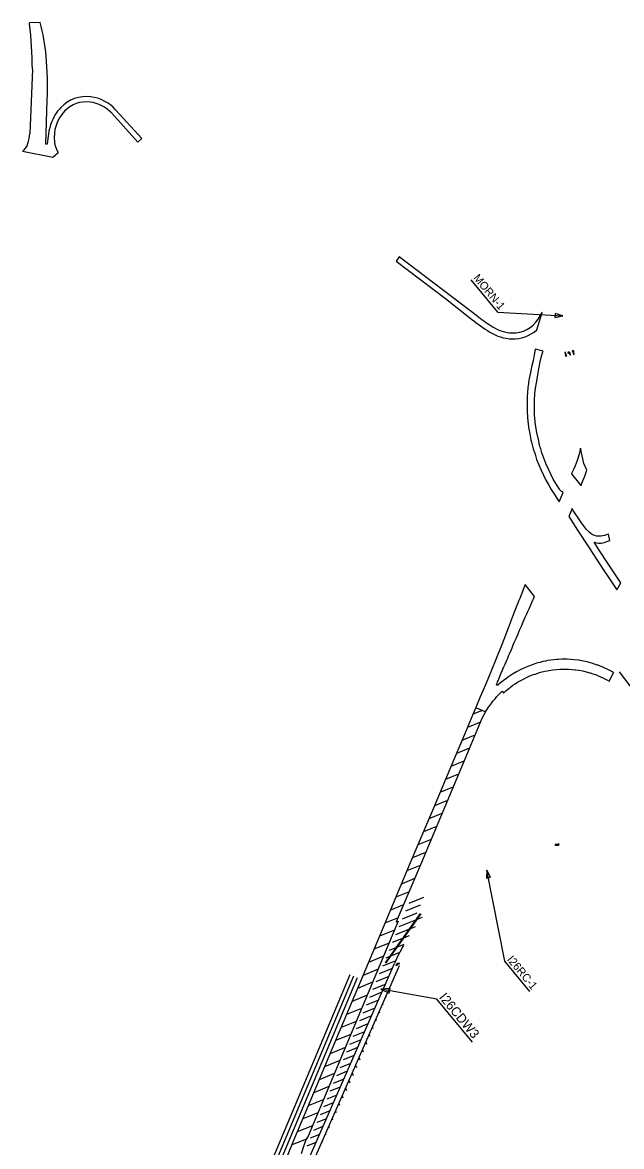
# Model space of a CAD drawing. Extents: x 1966356 to 1974207, y 790684 to 800034.
# Drawn here: x 1967744 to 1969541, y 796663 to 800034 of the extents above; entities that cross this region are included whole.
import ezdxf

# ---------------------------------------------------------------- set-up
doc = ezdxf.new("R2010")
doc.units = 0
for name, color, linetype in [('RD_EX_Pavement_Markings', 7, 'Continuous'), ('RD_PD_ALT5_LnLine', 7, 'Continuous'), ('RD_QTY_RemExConc', 7, 'Continuous'), ('RD_TX_RoadID', 7, 'Continuous'), ('TR_WZ_Temp Conc Barrier', 7, 'Continuous')]:
    doc.layers.add(name, color=color, linetype=linetype)

msp = doc.modelspace()

# ---------------------------------------------------------------- linework, layer by layer
at = {"layer": 'RD_EX_Pavement_Markings'}
for p, q in [((1968725.9, 797177.9), (1968434.7, 796483.7)), ((1968737, 797173.5), (1968445.8, 796479)), ((1968748.2, 797169), (1968456.8, 796474.4))]:
    msp.add_line(p, q, dxfattribs=at)
at = {"layer": 'RD_PD_ALT5_LnLine'}
for p, q in [((1969534, 798086.5), (1969927.6, 797568.6)), ((1969104.1, 797979.3), (1969095.1, 797957.9)), ((1969124.4, 797970.8), (1969095.5, 797959)), ((1969104.1, 797979.3), (1969133.7, 797966.8)), ((1969095.1, 797957.9), (1969070.2, 797898.8)), ((1969118.1, 797935.8), (1969079, 797919.8)), ((1969070.2, 797898.8), (1969050.4, 797851.9)), ((1969101.6, 797896.6), (1969062.5, 797880.6)), ((1969050.4, 797851.9), (1969031.1, 797806)), ((1969085, 797857.4), (1969046, 797841.5)), ((1969031.1, 797806), (1968977, 797677.9)), ((1969068.5, 797818.3), (1969029.5, 797802.3)), ((1969052, 797779.1), (1969013, 797763.1)), ((1969035.6, 797740), (1968996.5, 797724)), ((1969019.2, 797700.8), (1968979.9, 797684.8)), ((1968977, 797677.9), (1968924.5, 797553.2)), ((1969002.7, 797661.7), (1968963.4, 797645.6)), ((1968986.3, 797622.6), (1968947, 797606.5)), ((1968969.9, 797583.4), (1968930.5, 797567.3)), ((1968924.5, 797553.2), (1968907.7, 797513.1)), ((1968953.5, 797544.3), (1968914, 797528.2)), ((1968907.7, 797513.1), (1968828.6, 797325)), ((1968937, 797505.2), (1968897.6, 797489.1)), ((1968920.5, 797466), (1968881.1, 797449.9)), ((1968903.9, 797426.8), (1968864.7, 797410.8)), ((1968947.5, 797409.8), (1968903, 797391.6)), ((1968887.4, 797387.6), (1968848.2, 797371.6)), ((1968927.8, 797362.8), (1968883.3, 797344.6)), ((1968937.7, 797386.3), (1968893.2, 797368.1)), ((1968828.6, 797325), (1968760.5, 797163)), ((1968870.9, 797348.5), (1968831.7, 797332.5)), ((1968943.8, 797349.9), (1968873.5, 797321.1)), ((1968860.4, 797311.8), (1968815.3, 797293.3)), ((1968904.5, 797294.9), (1968853.8, 797274.2)), ((1968922.6, 797321.8), (1968863.6, 797297.7)), ((1968844, 797272.7), (1968798.8, 797254.2)), ((1968888.4, 797268.9), (1968843.9, 797250.7)), ((1968827.6, 797233.5), (1968782.4, 797215)), ((1968875.6, 797244.2), (1968834.1, 797227.2)), ((1968541.9, 796446), (1968875, 797205.5)), ((1968571.4, 796553.1), (1968860.3, 797212)), ((1968811.1, 797194.4), (1968765.9, 797175.9)), ((1968853.4, 797196.2), (1968814.4, 797180.3)), ((1968863.9, 797220), (1968824.2, 797203.8)), ((1968760.5, 797163), (1968694.6, 797006.4)), ((1968794.7, 797155.3), (1968749.5, 797136.8)), ((1968843, 797172.5), (1968804.6, 797156.8)), ((1968822.2, 797125.1), (1968784.9, 797109.9)), ((1968832.6, 797148.8), (1968794.7, 797133.3)), ((1968778.3, 797116.1), (1968733, 797097.6)), ((1968811.9, 797101.4), (1968775, 797086.4)), ((1968824.2, 797089.8), (1968825.3, 797087.3)), ((1968834.3, 797112.8), (1968835.1, 797110.8)), ((1968761.8, 797077), (1968716.5, 797058.5)), ((1968801.5, 797077.8), (1968765.2, 797062.9)), ((1968814.2, 797066.9), (1968815.4, 797063.8)), ((1968745.4, 797037.9), (1968700, 797019.3)), ((1968780.7, 797030.4), (1968745.5, 797016)), ((1968791.1, 797054.1), (1968755.3, 797039.4)), ((1968794, 797021), (1968795.7, 797016.9)), ((1968804.1, 797043.9), (1968805.6, 797040.3)), ((1968694.6, 797006.4), (1968593.6, 796765.9)), ((1968729, 796998.7), (1968683.6, 796980.2)), ((1968770.3, 797006.7), (1968735.6, 796992.5)), ((1968784, 796998), (1968785.9, 796993.4)), ((1968712.6, 796959.6), (1968667.2, 796941)), ((1968749.5, 796959.3), (1968715.9, 796945.5)), ((1968759.9, 796983), (1968725.8, 796969)), ((1968773.9, 796975.1), (1968776, 796969.9)), ((1968696.1, 796920.5), (1968650.7, 796901.9)), ((1968739.1, 796935.6), (1968706.1, 796922.1)), ((1968753.8, 796929.2), (1968756.4, 796923)), ((1968763.9, 796952.2), (1968766.2, 796946.4)), ((1968718.3, 796888.2), (1968686.4, 796875.1)), ((1968728.7, 796911.9), (1968696.3, 796898.6)), ((1968743.7, 796906.3), (1968746.5, 796899.5)), ((1968679.7, 796881.3), (1968634.3, 796862.8)), ((1968707.9, 796864.5), (1968676.6, 796851.6)), ((1968723.6, 796860.4), (1968726.5, 796853.3)), ((1968733.7, 796883.3), (1968736.7, 796876)), ((1968663.3, 796842.2), (1968617.9, 796823.6)), ((1968697.6, 796840.8), (1968666.7, 796828.2)), ((1968713.6, 796837.4), (1968716.1, 796831.1)), ((1968646.8, 796803.1), (1968601.5, 796784.5)), ((1968676.8, 796793.4), (1968647, 796781.2)), ((1968687.2, 796817.1), (1968656.9, 796804.7)), ((1968693.4, 796791.5), (1968695.4, 796786.7)), ((1968703.5, 796814.5), (1968705.8, 796808.9)), ((1968593.6, 796765.9), (1968557.8, 796680.2)), ((1968630.4, 796763.9), (1968585.1, 796745.4)), ((1968666.4, 796769.7), (1968637.2, 796757.7)), ((1968683.4, 796768.6), (1968685, 796764.5)), ((1968614, 796724.8), (1968568.7, 796706.3)), ((1968645.6, 796722.3), (1968617.5, 796710.8)), ((1968656, 796746), (1968627.3, 796734.3)), ((1968663.2, 796722.7), (1968664.3, 796720.1)), ((1968673.3, 796745.6), (1968674.7, 796742.3)), ((1968596, 796685), (1968552.4, 796667.2)), ((1968635.2, 796698.6), (1968607.6, 796687.3)), ((1968653.2, 796699.7), (1968653.9, 796697.9)), ((1968557.8, 796680.2), (1968491, 796520.4)), ((1968624.8, 796674.9), (1968597.8, 796663.8)), ((1968643.1, 796676.8), (1968643.6, 796675.7))]:
    msp.add_line(p, q, dxfattribs=at)
for points in [[(1969373.5, 799044.7), (1969371.2, 799044.1), (1969373.5, 799035.2), (1969371.9, 799034.8), (1969375.3, 799032.7), (1969377.4, 799036.2), (1969375.8, 799035.8)], [(1969388.5, 799037.3), (1969387.2, 799042.5), (1969383.4, 799044.8), (1969384.2, 799046.2), (1969380.3, 799045.2), (1969381.3, 799041.3), (1969382.2, 799042.7), (1969385.1, 799040.9), (1969386.2, 799036.7)], [(1969397.3, 799038.3), (1969399.6, 799038.9), (1969397.4, 799047.8), (1969399, 799048.2), (1969395.5, 799050.2), (1969393.5, 799046.8), (1969395.1, 799047.2)], [(1969342.5, 797568.7), (1969342.7, 797566.3), (1969351.8, 797566.8), (1969351.9, 797565.2), (1969354.6, 797568.2), (1969351.6, 797570.8), (1969351.7, 797569.2)], [(1968865.3, 797205.8), (1968867.3, 797210.7), (1968871.5, 797212.4), (1968870.9, 797213.9), (1968874.6, 797212.4), (1968873, 797208.7), (1968872.4, 797210.2), (1968869.2, 797208.9), (1968867.5, 797204.9)]]:
    msp.add_lwpolyline(points, close=True, dxfattribs=at)
msp.add_lwpolyline([(1969133.7, 797966.8), (1969122.6, 797946.3), (1969099.5, 797891.6), (1969079.1, 797843.5), (1968964, 797569.4), (1968944, 797521.7), (1968865.8, 797336.4), (1968871.5, 797338.1), (1968600.9, 796693.7), (1968594.7, 796682.8), (1968588.5, 796665.2), (1968580, 796640.7)], dxfattribs=at)
msp.add_arc((1969424.5, 796964.6), 616, 150.713, 156.3246, dxfattribs=at)
at = {"layer": 'RD_QTY_RemExConc'}
for p, q in [((1967797.2, 800034.1), (1967765.4, 800033.5)), ((1967774, 799894.3), (1967770.3, 799796.3)), ((1967770.3, 799796.3), (1967766, 799701.3)), ((1967814, 799669.5), (1967818.9, 799801.7)), ((1968012, 799761.7), (1968090.4, 799675.1)), ((1968102.3, 799685.9), (1968023.9, 799772.4)), ((1968090.4, 799675.1), (1968102.3, 799685.9)), ((1967818.8, 799669.2), (1967814, 799669.5)), ((1967744.4, 799647.6), (1967835.1, 799629.9)), ((1967835.1, 799629.9), (1967851.8, 799643.7)), ((1968874.6, 799331.3), (1968864.9, 799318.6)), ((1968864.9, 799318.6), (1969013.4, 799205.9)), ((1969111.8, 799151.3), (1968874.6, 799331.3)), ((1969013.4, 799205.9), (1969091.2, 799144.5)), ((1969287.1, 799111.9), (1969303.4, 799164.6)), ((1969303.4, 799164.6), (1969302.4, 799164.7)), ((1969306.3, 799048.4), (1969282.4, 799054)), ((1969393, 798575.9), (1969382.9, 798551.9)), ((1969506.8, 798480.8), (1969502.2, 798499.7)), ((1969280.1, 798312.8), (1969252.6, 798348.5)), ((1969527.3, 798332.3), (1969539.4, 798353.8)), ((1969280, 798312.7), (1969280.1, 798312.8)), ((1969257.6, 798260.4), (1969260.4, 798267)), ((1969517, 798084), (1969504, 798058.4)), ((1969504, 798058.4), (1969517, 798084)), ((1969104.1, 797979.3), (1969133.7, 797966.8))]:
    msp.add_line(p, q, dxfattribs=at)
for points in [[(1967859, 799778.9), (1967859, 799778.9)], [(1967870.6, 799767.9), (1967870.6, 799767.9)], [(1969282.4, 799054), (1969279.4, 799037.2), (1969276.3, 799019.7), (1969272.5, 799005.2), (1969267.9, 798984.7), (1969264.4, 798966), (1969263.5, 798960.7), (1969262.7, 798955.4), (1969262, 798950.1), (1969261.3, 798944.8), (1969260.7, 798939.4), (1969260.1, 798934.1), (1969259.6, 798928.7), (1969259.2, 798923.4), (1969259, 798920.9), (1969258.7, 798915.4), (1969258.4, 798909.8), (1969258.2, 798904.3), (1969258, 798898.7), (1969258, 798893.2), (1969257.9, 798887.6), (1969258, 798882), (1969258, 798878.2), (1969258.2, 798872.4), (1969258.4, 798866.5), (1969258.7, 798860.7), (1969258.9, 798858.1), (1969259.3, 798852.4), (1969259.7, 798846.6), (1969260.2, 798840.9), (1969260.8, 798835.1), (1969260.9, 798834.3), (1969261.5, 798828.7), (1969262.2, 798823.2), (1969262.6, 798820.6), (1969266, 798800), (1969269.5, 798782.7), (1969271.2, 798775.1), (1969276.8, 798754.8), (1969281.9, 798739.1), (1969286.6, 798723.7), (1969292.9, 798706.9), (1969300.2, 798691), (1969306.9, 798676.1), (1969314.8, 798660.9), (1969323, 798646.2), (1969330.6, 798632.8), (1969340.1, 798618.2), (1969354.5, 798596)], [(1969366.1, 798623.9), (1969363.1, 798626.3), (1969361.4, 798627.6), (1969360.4, 798628.3), (1969359.4, 798629.2), (1969358.4, 798630.1), (1969357.4, 798631.1), (1969356.5, 798632.1), (1969355.7, 798633.1), (1969354.9, 798634.2), (1969346, 798647.8), (1969336.5, 798664.6), (1969329.3, 798678.9), (1969322, 798694.3), (1969314.8, 798711), (1969308.5, 798727.3), (1969302.7, 798743.7), (1969301.6, 798746.9), (1969300.3, 798750.8), (1969299.1, 798754.8), (1969297.9, 798758.7), (1969296.8, 798762.7), (1969291.9, 798783.1), (1969287.3, 798804.7), (1969283.5, 798827.4), (1969281.5, 798845.9), (1969280.8, 798857.6), (1969280.1, 798877.3), (1969280.3, 798900), (1969281.5, 798920.4), (1969283.6, 798936.9), (1969287, 798957.9), (1969290.2, 798977.4), (1969293, 798995.2), (1969296.1, 799011.2), (1969300.3, 799030.4), (1969305.6, 799046.5), (1969306.3, 799048.4)], [(1969418.7, 798757.5), (1969414.4, 798738.8), (1969408.5, 798720.1), (1969402.3, 798704.4), (1969397.2, 798693.4), (1969392.8, 798683), (1969391.8, 798680.6)], [(1969437.5, 798691.5), (1969427.9, 798711.6), (1969418.7, 798757.5)], [(1969391.8, 798680.6), (1969391.8, 798680.6), (1969419.1, 798645)], [(1969419.9, 798645.7), (1969422.5, 798652.5), (1969425.4, 798659.7), (1969431.1, 798673.3), (1969437.5, 798691.5)], [(1969354.5, 798596), (1969354.7, 798596.4), (1969366.1, 798623.9)], [(1969502.2, 798499.7), (1969501.4, 798499.2), (1969499.2, 798498.1), (1969490.6, 798495), (1969485, 798494.1), (1969479.3, 798493.5), (1969473.6, 798493.3), (1969467.9, 798493.5), (1969466, 798493.6), (1969461.7, 798494.9), (1969457.6, 798496.5), (1969453.6, 798498.5), (1969450.5, 798500.3), (1969444.8, 798505), (1969439.4, 798509.9), (1969435.1, 798514.2), (1969419.3, 798536.2), (1969396.7, 798570.3), (1969393, 798575.9)], [(1969382.9, 798551.9), (1969409.5, 798511.2), (1969443.9, 798458.2), (1969486.7, 798393.5), (1969503.5, 798368.2), (1969527.3, 798332.3)], [(1969539.4, 798353.8), (1969527.2, 798371.8), (1969499.6, 798413.6), (1969474.8, 798451.3), (1969459.1, 798475.1), (1969463.2, 798473.9), (1969467.5, 798473), (1969471.9, 798472.5), (1969476.3, 798472.4), (1969480.6, 798472.7), (1969484.9, 798473.3), (1969489.2, 798474.4), (1969491.9, 798475.3), (1969497.7, 798477.1), (1969503.4, 798479.2), (1969506.8, 798480.8)], [(1969252.6, 798348.5), (1969251.5, 798345.8), (1969249.2, 798340.4), (1969246.5, 798333.8), (1969242.9, 798324.7), (1969239, 798314.5), (1969235.9, 798306.5), (1969233.5, 798300.2)], [(1969260.4, 798267), (1969263.9, 798275.1), (1969269, 798287.7), (1969274.5, 798299.3), (1969277.1, 798305.4), (1969280, 798312.6), (1969280, 798312.7)], [(1969233, 798300.8), (1969219.2, 798265), (1969201, 798217), (1969182.9, 798170), (1969164, 798123), (1969151.3, 798091.6), (1969132.9, 798047.4), (1969117.7, 798011.8), (1969104.1, 797979.3)], [(1969170.9, 798047.1), (1969170.2, 798046.3), (1969169.3, 798046), (1969168.3, 798045.9), (1969167.8, 798046.1), (1969167.2, 798046.4), (1969166.6, 798047.3), (1969166.4, 798048.2), (1969168.3, 798052.6), (1969169.6, 798056.3), (1969170.9, 798059.6), (1969171.7, 798061.1), (1969172.1, 798062.3), (1969172.9, 798064.3), (1969174.5, 798067.8), (1969175.7, 798070), (1969176.5, 798071.9), (1969177.3, 798074.9), (1969179.5, 798080.3), (1969181.4, 798085), (1969183.1, 798088.7), (1969185.4, 798094.6), (1969188.2, 798101.2), (1969192, 798109.5), (1969194.9, 798116), (1969197.3, 798121.8), (1969199.9, 798127.7), (1969202.7, 798134.3), (1969205.4, 798140.7), (1969210.9, 798153.2), (1969213.2, 798158.5), (1969216.8, 798167.2), (1969216.8, 798167.2), (1969220.8, 798176.8), (1969225.2, 798186.7), (1969231.5, 798200.7), (1969235.8, 798211.1), (1969241.1, 798223.8), (1969246.5, 798236.3), (1969252.7, 798250.5), (1969257.6, 798260.4)], [(1969376.6, 798124.3), (1969372.3, 798124.4), (1969361.9, 798124.3), (1969351.5, 798123.8), (1969347.3, 798123.6), (1969338.3, 798122.8), (1969329.3, 798121.6), (1969320.4, 798120), (1969316.1, 798119.1), (1969314.4, 798118.8), (1969305.8, 798117), (1969297.2, 798114.8), (1969296.3, 798114.6), (1969286.3, 798111.9), (1969276.4, 798108.8), (1969265.7, 798104.7), (1969250.4, 798098.4), (1969248.5, 798097.5), (1969237.4, 798092.1), (1969226.5, 798086.3), (1969226.1, 798086.1), (1969214.2, 798078.9), (1969202.6, 798071.3), (1969193.2, 798064.7), (1969186.4, 798059.7), (1969178.3, 798053.4), (1969170.9, 798047.1)], [(1969477.8, 798103.5), (1969471, 798105.9), (1969468.8, 798106.8), (1969460.6, 798109.8), (1969452.3, 798112.5), (1969443.9, 798114.7), (1969442.7, 798115), (1969432.5, 798117.4), (1969422.3, 798119.4), (1969411.9, 798121), (1969411.1, 798121.2), (1969400.3, 798122.6), (1969389.5, 798123.6), (1969378.7, 798124.3), (1969376.6, 798124.3)], [(1969517, 798084), (1969516.4, 798084.4), (1969509.9, 798088.4), (1969504.2, 798091.5), (1969498.2, 798094.4), (1969489.2, 798098.5), (1969481.1, 798102.2), (1969477.8, 798103.5)], [(1969208.8, 798040.8), (1969215.4, 798045.9), (1969222.3, 798050.6), (1969229.4, 798055), (1969235.8, 798058.6), (1969247.7, 798064.8), (1969258.4, 798070.2), (1969264.6, 798073.3), (1969270.9, 798075.9), (1969277.4, 798078.2), (1969282.9, 798079.8), (1969290.6, 798082.6), (1969298.4, 798085), (1969303.1, 798086.3), (1969311.1, 798088.2), (1969319.3, 798089.8), (1969323.1, 798090.4), (1969335.1, 798092.2), (1969347.1, 798093.6), (1969356, 798094.4), (1969369.3, 798094.7), (1969382.7, 798094.7), (1969383.7, 798094.6), (1969393.8, 798093.8), (1969402.3, 798092.8)], [(1969402.3, 798092.8), (1969403.9, 798092.6), (1969413.9, 798091), (1969414.4, 798091), (1969425.1, 798088.9), (1969435.7, 798086.4), (1969446.2, 798083.6), (1969447.2, 798083.3), (1969455.4, 798080.8), (1969463.5, 798078), (1969471.5, 798074.7), (1969474.3, 798073.5), (1969489, 798066.2), (1969489.2, 798066), (1969497.1, 798062.2), (1969504, 798058.4)], [(1969133.7, 797966.8), (1969137.5, 797972.8), (1969142.8, 797980.6), (1969146.5, 797985.7), (1969152, 797993), (1969155.6, 797998), (1969162, 798005.6), (1969167.7, 798012.3), (1969176.2, 798021.8), (1969183, 798028.7), (1969184.6, 798026.9), (1969187.8, 798023.2), (1969188.3, 798023.7), (1969195.6, 798030.2), (1969203.1, 798036.4), (1969208.8, 798040.8)]]:
    msp.add_lwpolyline(points, dxfattribs=at)
for centre, radius, start, end in [((1967388.1, 799987.9), 380.1, 6.3358, 6.8843), ((1966421.4, 799880.6), 1352.7, 0.5783, 6.3358), ((1967246.9, 799882.3), 570.8, 5.1407, 15.4166), ((1966779.2, 799840.3), 1040.4, 357.8779, 5.1407), ((1967936.2, 799705.4), 106.6, 83.141, 136.3598), ((1967936.2, 799705.4), 90.6, 83.141, 136.3598), ((1967934.5, 799691.4), 104.6, 42.1797, 83.141), ((1967934.5, 799691.4), 120.6, 42.1797, 83.141), ((1967952.3, 799690), 128.8, 136.3601, 161.8673), ((1967952.3, 799690), 112.8, 136.3601, 187.2518), ((1968045.8, 799659.4), 227.2, 161.8673, 177.5348), ((1967642.6, 799706.9), 123.5, 343.1721, 357.4252), ((1967715.3, 799685.5), 47.8, 307.4791, 342.4158), ((1967918.9, 799685.8), 79.2, 187.2518, 212.108), ((1969492.6, 799653.1), 647.9, 231.7182, 237.7175), ((1969492.6, 799653.1), 629.9, 232.8066, 237.7175), ((1969149, 799235.1), 168.8, 327.4072, 335.3308), ((1969216.8, 799216.6), 113.6, 237.7175, 268.1832), ((1969216, 799192.3), 107.3, 268.1832, 311.4832), ((1969216, 799192.3), 89.3, 268.1832, 327.4072), ((1969216.8, 799216.6), 131.6, 237.7175, 268.1832), ((1969420.7, 798643.9), 2, 114.5333, 146.3425)]:
    msp.add_arc(centre, radius, start, end, dxfattribs=at)
at = {"layer": 'RD_TX_RoadID'}
for p, q in [((1969170.3, 799165.2), (1969089.9, 799262.6)), ((1969266.4, 797127.2), (1969191, 797218.5)), ((1969094, 796975.3), (1968987.1, 797104.8))]:
    msp.add_line(p, q, dxfattribs=at)
for points in [[(1969170.3, 799165.2), (1969365, 799154.1)], [(1969191, 797218.5), (1969137.6, 797491.6)], [(1968987.1, 797104.8), (1968819, 797134.4)]]:
    msp.add_lwpolyline(points, dxfattribs=at)
for points in [[(1969341.5, 799149.2), (1969365, 799154.1), (1969342.2, 799161.6)], [(1969148.2, 797470.1), (1969137.6, 797491.6), (1969136, 797467.7)], [(1968846.9, 797136.8), (1968819, 797134.4), (1968844.4, 797122.6)]]:
    msp.add_lwpolyline(points, close=True, dxfattribs=at)
at = {"layer": 'TR_WZ_Temp Conc Barrier'}
for p, q in [((1968937.8, 797361.5), (1968832.1, 797213.8)), ((1968939.5, 797360.4), (1968833.7, 797212.6))]:
    msp.add_line(p, q, dxfattribs=at)

# ---------------------------------------------------------------- texts
at = {"layer": 'RD_TX_RoadID'}
for s, height, p in [('MORN-1', 24, (1969095.3, 799267)), ('I26RC-1', 24, (1969196.4, 797222.9)), ('I26CDW3', 28, (1968992.5, 797109.2))]:
    msp.add_text(s, height=height, rotation=309.5517, dxfattribs=at).set_placement(p)

doc.saveas('drawing.dxf')
